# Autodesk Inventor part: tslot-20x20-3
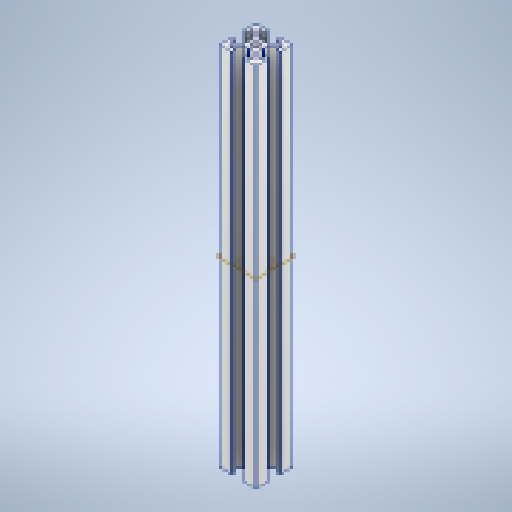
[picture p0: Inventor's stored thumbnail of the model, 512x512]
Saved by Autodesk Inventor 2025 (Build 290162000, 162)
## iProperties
Created: 2025-03
Part Number: tslot-20x20-3
Material: Alluminio 6061
Document SubType Name: Modeling
Designer: Ryzen5700u
Density: 2.7 g/cm^3
Appearance: Alluminio - Piatto
Author: Ryzen5700u
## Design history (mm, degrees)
feature "Base1"
sketch "Schizzo1"
  geometry: L1 (3.761, -16)-(4.7, -16) reference; L2 (3.761, -16)-(0.7, -12.939) reference; L3 (0.7, -12.939)-(0.7, -10.52) reference; L4 (0.4, -10)-(0.7, -10.52) reference; L5 (0.4, -10)-(0.7, -9.48) reference; L6 (0.7, -7.061)-(0.7, -9.48) reference; L7 (3.761, -4)-(0.7, -7.061) reference; L8 (3.761, -4)-(4.7, -4) reference; L9 (4.7, -4)-(4.7, -7) reference; L10 (4.7, -7)-(6.4, -7) reference; L11 (6.7, -6.7)-(6.7, -1) reference; L12 (5.7, 0)-(0, 0) reference; L13 (-0.3, -2)-(-0.3, -0.3) reference; L14 (2.7, -2)-(-0.3, -2) reference; L15 (2.7, -2.939)-(2.7, -2) reference; L16 (2.7, -2.939)-(-0.361, -6) reference; L17 (-0.361, -6)-(-2.78, -6) reference; L18 (-3.3, -6.3)-(-2.78, -6) reference; L19 (-3.3, -6.3)-(-3.82, -6) reference; L20 (-6.239, -6)-(-3.82, -6) reference; L21 (-9.3, -2.939)-(-6.239, -6) reference; L22 (-9.3, -2.939)-(-9.3, -2) reference; L23 (-9.3, -2)-(-6.3, -2) reference; L24 (-6.3, -2)-(-6.3, -0.3) reference; L25 (-12.3, 0)-(-6.6, 0) reference; L26 (-13.3, -6.7)-(-13.3, -1) reference; L27 (-11.3, -7)-(-13, -7) reference; L28 (-11.3, -4)-(-11.3, -7) reference; L29 (-10.361, -4)-(-11.3, -4) reference; L30 (-10.361, -4)-(-7.3, -7.061) reference; L31 (-7.3, -7.061)-(-7.3, -9.48) reference; L32 (-7, -10)-(-7.3, -9.48) reference; L33 (-7, -10)-(-7.3, -10.52) reference; L34 (-7.3, -12.939)-(-7.3, -10.52) reference; L35 (-10.361, -16)-(-7.3, -12.939) reference; L36 (-10.361, -16)-(-11.3, -16) reference; L37 (-11.3, -16)-(-11.3, -13) reference; L38 (-11.3, -13)-(-13, -13) reference; L39 (-13.3, -13.3)-(-13.3, -19) reference; L40 (-12.3, -20)-(-6.6, -20) reference; L41 (-6.3, -18)-(-6.3, -19.7) reference; L42 (-9.3, -18)-(-6.3, -18) reference; L43 (-9.3, -17.061)-(-9.3, -18) reference; L44 (-9.3, -17.061)-(-6.239, -14) reference; L45 (-6.239, -14)-(-3.82, -14) reference; L46 (-3.3, -13.7)-(-3.82, -14) reference; L47 (-3.3, -13.7)-(-2.78, -14) reference; L48 (-0.361, -14)-(-2.78, -14) reference; L49 (2.7, -17.061)-(-0.361, -14) reference; L50 (2.7, -17.061)-(2.7, -18) reference; L51 (2.7, -18)-(-0.3, -18) reference; L52 (-0.3, -18)-(-0.3, -19.7) reference; L53 (5.7, -20)-(0, -20) reference; L54 (6.7, -13.3)-(6.7, -19) reference; L55 (4.7, -13)-(6.4, -13) reference; L56 (4.7, -16)-(4.7, -13) reference; C1 r 2.1 at (-3.3, -10) reference; A1 r 0.3 centre (6.4, -6.7) between (6.4, -7) and (6.7, -6.7) reference; A2 r 1 centre (5.7, -1) between (6.7, -1) and (5.7, 0) reference; A3 r 0.3 centre (0, -0.3) between (0, 0) and (-0.3, -0.3) reference; A4 r 0.3 centre (-6.6, -0.3) between (-6.3, -0.3) and (-6.6, 0) reference; A5 r 1 centre (-12.3, -1) between (-12.3, 0) and (-13.3, -1) reference; A6 r 0.3 centre (-13, -6.7) between (-13.3, -6.7) and (-13, -7) reference; A7 r 0.3 centre (-13, -13.3) between (-13, -13) and (-13.3, -13.3) reference; A8 r 1 centre (-12.3, -19) between (-13.3, -19) and (-12.3, -20) reference; A9 r 0.3 centre (-6.6, -19.7) between (-6.6, -20) and (-6.3, -19.7) reference; A10 r 0.3 centre (0, -19.7) between (-0.3, -19.7) and (0, -20) reference; A11 r 1 centre (5.7, -19) between (5.7, -20) and (6.7, -19) reference; A12 r 0.3 centre (6.4, -13.3) between (6.7, -13.3) and (6.4, -13) reference; 1 further point
extrude "Estrusione1" join sketch "Schizzo1" distance "d0" = 190; taper "d1" = 0 deg
node "Piano di lavoro1"
node "Solido1"
node "Linea chiusa proiettata1"
